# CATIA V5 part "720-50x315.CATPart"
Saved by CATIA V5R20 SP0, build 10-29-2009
Part number: 720-50x315
Definition: NONE
Nomenclature: 720-50x315
Source: Unknown
Description: 720-50x315
Bounding box of the stored display mesh (mm): x 0 to 315, y -25 to 25, z -25 to 25
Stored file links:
  C:\Users\Utente\Desktop\IO LAVORO\3D X SITO CF\X SITO\720\720-50x315.CATPart
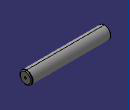
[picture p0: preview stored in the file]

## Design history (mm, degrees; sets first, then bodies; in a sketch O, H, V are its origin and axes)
Body1 "720-50x315" (main body)
  Solid1: solid without history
